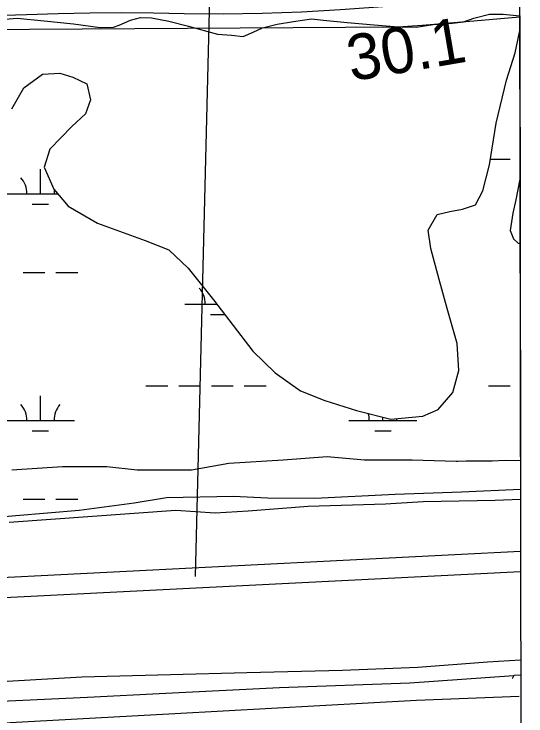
# Model space of a CAD drawing. Extents: x 3297772 to 3335630, y 634068 to 659439.
# Drawn here: x 3332702 to 3333452, y 644761 to 645791 of the extents above; entities that cross this region are included whole.
import ezdxf

# ---------------------------------------------------------------- set-up
doc = ezdxf.new("R2010")
doc.units = 0
for name, color, linetype in [('V-GRID-FRAM', 7, 'Continuous'), ('V-LEVE-TOET', 7, 'Continuous'), ('V-RIVR-EDGE', 7, 'Continuous'), ('V-RIVR-RANG', 7, 'Continuous'), ('V-ROAD-CNTR', 7, 'Continuous'), ('V-SITE-VEGE', 7, 'Continuous'), ('V-SURV-LINE', 7, 'Continuous'), ('V-TOPO-MAJR', 7, 'Continuous'), ('V-TOPO-MINR', 7, 'Continuous'), ('V-TOPO-SHOR', 7, 'Continuous'), ('V-WETL-SWMP', 7, 'Continuous')]:
    doc.layers.add(name, color=color, linetype=linetype)

msp = doc.modelspace()

# ---------------------------------------------------------------- linework, layer by layer
at = {"layer": 'V-GRID-FRAM'}
msp.add_lwpolyline([(3301870.2, 657630.6), (3333425.5, 657662.7), (3333452, 639478.7), (3301880.8, 639446.5), (3301870.2, 657630.6)], dxfattribs=at)
at = {"layer": 'V-LEVE-TOET'}
for points in [[(3332694.6, 645045.6), (3332938.6, 645062.9), (3332996.5, 645059.3), (3333045, 645062), (3333132.9, 645068.9), (3333246.3, 645072.3), (3333301.5, 645075.7), (3333407.1, 645077.6), (3333443.8, 645079.2)], [(3333444.2, 644843.2), (3333395.7, 644840.3), (3333293.6, 644832.2), (3333182.9, 644827.7), (3333042.9, 644824.3), (3332931.1, 644821.7), (3332801.3, 644817.9), (3332691.4, 644811.8)]]:
    msp.add_lwpolyline(points, dxfattribs=at)
at = {"layer": 'V-RIVR-EDGE'}
msp.add_spline([(3330448.9, 645637.2), (3330473.8, 645644.9), (3330485.1, 645645.6), (3330500.5, 645644.8), (3330522, 645643.6), (3330539.6, 645642.9), (3330563, 645640.3), (3330599.1, 645635.4), (3330611.9, 645635.4), (3330614.5, 645637.6), (3330621.8, 645642.7), (3330634.6, 645644.5), (3330658, 645645.1), (3330676.3, 645641.4), (3330692.7, 645638.8), (3330694.2, 645635.2), (3330695.6, 645630.4), (3330718.3, 645625.6), (3330735.1, 645623.7), (3330742.4, 645624.5), (3330747.5, 645627), (3330751.6, 645631.4), (3330753.4, 645635), (3330761.1, 645637.2), (3330782.3, 645640.8), (3330789.2, 645640.4), (3330794, 645636), (3330802.7, 645623.9), (3330811.5, 645611.5), (3330815.5, 645603.8), (3330821.3, 645595.7), (3330822, 645586.6), (3330823.1, 645574.9), (3330824.5, 645569.1), (3330830.7, 645561.4), (3330835.5, 645561), (3330841.3, 645561), (3330847.2, 645568.6), (3330850.1, 645570.1), (3330855.2, 645571.5), (3330860, 645570.4), (3330868, 645567.8), (3330875, 645567.5), (3330884.1, 645569.3), (3330893.3, 645573.3), (3330905.3, 645585.3), (3330916, 645598.1), (3330920.4, 645599.5), (3330923.7, 645599.9), (3330931.3, 645596.6), (3330964.5, 645574.2), (3330990.5, 645558), (3331006.9, 645555.8), (3331027.4, 645556.5), (3331050.4, 645560.8), (3331062.5, 645564.1), (3331069.8, 645569.2), (3331073.8, 645575.4), (3331079, 645581.6), (3331080.5, 645593.3), (3331079, 645606.8), (3331077.6, 645625.5), (3331079.1, 645633.5), (3331082, 645639.7), (3331082.4, 645641.5), (3331081, 645646.3), (3331082.1, 645648.1), (3331083.5, 645650.3), (3331090.5, 645655), (3331104.4, 645656.5), (3331108.8, 645656.4), (3331111.7, 645653.9), (3331119, 645651.3), (3331128.1, 645649.8), (3331136.9, 645646.1), (3331145.3, 645644.3), (3331147.9, 645645), (3331151.9, 645649), (3331154.1, 645652.7), (3331158.5, 645654.9), (3331161.8, 645654.1), (3331162.5, 645650.5), (3331163.9, 645638.4), (3331166.1, 645632.2), (3331174.9, 645626.7), (3331193.5, 645621.5), (3331201.2, 645621.5), (3331209.2, 645624), (3331216.9, 645631), (3331220.6, 645637.9), (3331221.3, 645645.2), (3331221.7, 645651.1), (3331219.5, 645660.9), (3331219.6, 645665.3), (3331221.8, 645667.9), (3331223.2, 645668.6), (3331224, 645672.2), (3331224.3, 645674.1), (3331226.9, 645674.8), (3331232.7, 645674.1), (3331234.2, 645675.9), (3331234.6, 645678.4), (3331237.5, 645678.8), (3331243, 645677.3), (3331252.5, 645675.5), (3331262.3, 645674.7), (3331276.6, 645675.8), (3331288.3, 645677.6), (3331300.7, 645680.8), (3331309.2, 645688.1), (3331324.6, 645709.3), (3331338.9, 645733), (3331346.2, 645741.4), (3331353.5, 645744.7), (3331367.4, 645747.2), (3331376.9, 645748.6), (3331391.2, 645748.2), (3331400.7, 645747.1), (3331406.5, 645746.7), (3331412.4, 645748.5), (3331415.3, 645750), (3331416.4, 645747.8), (3331418.6, 645746.3), (3331424.1, 645746.3), (3331431.8, 645750.3), (3331439.8, 645751), (3331465.1, 645752.4), (3331476, 645754.6), (3331481.5, 645759), (3331488.1, 645763.3), (3331494.3, 645765.9), (3331501.3, 645766.2), (3331514.4, 645765.5), (3331515.9, 645762.9), (3331517.7, 645761.1), (3331527.2, 645758.9), (3331536, 645758.8), (3331540.4, 645760.7), (3331541.1, 645762.5), (3331540.4, 645765), (3331536, 645768.3), (3331536, 645770.2), (3331537.1, 645771.6), (3331540, 645772), (3331557.6, 645767.9), (3331569.3, 645767.5), (3331581, 645767.5), (3331596, 645769.3), (3331613.5, 645772.2), (3331624.8, 645773.2), (3331630.3, 645771.4), (3331633.6, 645768.5), (3331638.7, 645767.7), (3331643.1, 645768.1), (3331648.6, 645770.6), (3331652.6, 645773.9), (3331660.3, 645775.7), (3331670.9, 645775.3), (3331678.2, 645771.3), (3331684.1, 645769.4), (3331691.4, 645768.7), (3331711.1, 645769.7), (3331753.5, 645776.2), (3331799.6, 645782.3), (3331827, 645783.3), (3331853, 645787.7), (3331887.7, 645791.2), (3331916.2, 645792.6), (3331931.2, 645791.9), (3331942.6, 645790), (3331955, 645781.9), (3331968.5, 645770.9), (3331978.3, 645765.4), (3332002.4, 645757.7), (3332022.2, 645755.8), (3332044.5, 645757.2), (3332072.2, 645760.4), (3332109.2, 645767.7), (3332134.1, 645770.9), (3332153.4, 645771.9), (3332163.7, 645772.6), (3332202.8, 645781), (3332228.8, 645786), (3332235, 645790), (3332245.6, 645799.1), (3332252.9, 645806.4), (3332260.3, 645810.4), (3332275.3, 645814), (3332289.5, 645815.5), (3332303.4, 645813.6), (3332324.6, 645804), (3332345.4, 645794.1), (3332361.1, 645788.6), (3332369.9, 645788.2), (3332383, 645788.9), (3332399.5, 645788.1), (3332415.2, 645784.8), (3332428.7, 645782.6), (3332441.5, 645781.8), (3332451.4, 645785.8), (3332467.5, 645793.8), (3332481.4, 645804), (3332490.5, 645806.9), (3332500.4, 645806.9), (3332507.4, 645806.5), (3332513.9, 645806.5), (3332520.9, 645807.2), (3332533.7, 645811.6), (3332542.5, 645814.8), (3332553.8, 645819.2), (3332575.4, 645826.1), (3332590, 645832.3), (3332610.2, 645843.2), (3332632.9, 645858.8), (3332647.2, 645866.5), (3332662.1, 645870.5), (3332681.2, 645871.2), (3332696.5, 645869.7), (3332706, 645868.5), (3332710.4, 645868.5), (3332715.9, 645870), (3332722.1, 645873.6), (3332725.4, 645873.6), (3332731.6, 645873.6), (3332741.5, 645868.8), (3332755.3, 645863.7), (3332763, 645864), (3332790.8, 645862.1), (3332817.5, 645861), (3332831.4, 645858.7), (3332832.8, 645859.5), (3332832.8, 645860.9), (3332831.4, 645863.1), (3332824.1, 645865.3), (3332823.7, 645867.5), (3332824.8, 645870.4), (3332827.7, 645872.3), (3332831, 645872.6), (3332842.7, 645870.8), (3332851.9, 645868.5), (3332854.4, 645868.5), (3332874.2, 645871.8), (3332895.4, 645875.4), (3332904.9, 645876.1), (3332914.8, 645876.1), (3332925, 645873.1), (3332938.1, 645867.2), (3332953.1, 645857.7), (3332967.7, 645851.8), (3332979.4, 645851.4), (3332987.8, 645848.8), (3332995.5, 645844.4), (3333020, 645841.8), (3333039, 645841.4), (3333050.7, 645843.2), (3333067.9, 645849), (3333089.1, 645857.4), (3333116.5, 645867.2), (3333136.3, 645871.5), (3333157.1, 645874), (3333175, 645874), (3333191.5, 645873.6), (3333203.5, 645875.4), (3333217.4, 645879), (3333230.6, 645878.9), (3333255.4, 645876), (3333267.5, 645876.3), (3333286.9, 645881.7), (3333304.1, 645884.2), (3333322.7, 645884.9), (3333341, 645886.7), (3333351.6, 645892.5), (3333363, 645899.8), (3333371.4, 645902), (3333390, 645904.1), (3333418.2, 645908.1), (3333442.6, 645911.2)], degree=3, dxfattribs=at)
at = {"layer": 'V-RIVR-RANG'}
msp.add_line((3332967.5, 644966), (3333004.6, 646465.6), dxfattribs=at)
at = {"layer": 'V-ROAD-CNTR'}
msp.add_lwpolyline([(3331179.9, 644989.5), (3331441, 645002.9), (3331521.1, 645001.9), (3331578.7, 644990.8), (3331648, 644970.9), (3331747.7, 644939.4), (3331871.6, 644891.7), (3331950.6, 644848.9), (3332022.3, 644803.4), (3332081, 644767.4), (3332152.5, 644748.8), (3332215.7, 644734.7), (3332344.8, 644731.4), (3332641.7, 644748.8), (3332937.5, 644764.7), (3333291.4, 644784.2), (3333441.9, 644790.5)], dxfattribs=at)
at = {"layer": 'V-SITE-VEGE'}
for p, q in [((3332675.5, 645782.2), (3332706.1, 645784.9)), ((3332706.1, 645784.9), (3332745.9, 645781)), ((3332872.5, 645781.6), (3332887.2, 645785.8)), ((3332887.2, 645785.8), (3332903, 645785)), ((3332903, 645785), (3332928.6, 645780.4)), ((3333111.2, 645779.8), (3333137.5, 645783.6)), ((3333137.5, 645783.6), (3333155.3, 645781.6)), ((3333360.4, 645779.5), (3333375.5, 645784.5)), ((3333375.5, 645784.5), (3333398.7, 645790.7)), ((3333398.7, 645790.7), (3333418.8, 645790.6)), ((3333418.8, 645790.6), (3333442.8, 645788)), ((3333442.8, 645788), (3333443.8, 645135.6)), ((3332745.9, 645781), (3332788.9, 645776.3)), ((3332788.9, 645776.3), (3332828, 645771.2)), ((3332847.7, 645771.6), (3332855.8, 645774.6)), ((3332855.8, 645774.6), (3332872.5, 645781.6)), ((3332928.6, 645780.4), (3332957.6, 645773)), ((3332957.6, 645773), (3333000.1, 645761.3)), ((3333065.9, 645770.5), (3333087.2, 645775.9)), ((3333087.2, 645775.9), (3333111.2, 645779.8)), ((3333155.3, 645781.6), (3333189.8, 645778.5)), ((3333189.8, 645778.5), (3333229.6, 645775)), ((3333229.6, 645775), (3333264.8, 645771.8)), ((3333264.8, 645771.8), (3333291.1, 645771.4)), ((3333291.1, 645771.4), (3333315.9, 645775.3)), ((3333315.9, 645775.3), (3333344.1, 645777.6)), ((3333344.1, 645777.6), (3333360.4, 645779.5)), ((3332828, 645771.2), (3332847.7, 645771.6)), ((3333037.7, 645757.8), (3333052.4, 645764.4)), ((3333052.4, 645764.4), (3333065.9, 645770.5)), ((3333000.1, 645761.3), (3333020.6, 645759.7)), ((3333020.6, 645759.7), (3333037.7, 645757.8)), ((3333096, 645136.6), (3333016.5, 645131.6)), ((3333160.7, 645141.5), (3333096, 645136.6)), ((3333215.4, 645136.6), (3333160.7, 645141.5)), ((3333285, 645136.6), (3333215.4, 645136.6)), ((3333349.7, 645134.5), (3333285, 645136.6)), ((3333352.2, 645134.5), (3333349.7, 645134.5)), ((3333364.4, 645134.8), (3333352.2, 645134.5)), ((3333369.9, 645134.8), (3333364.4, 645134.8)), ((3333389.2, 645135.1), (3333369.9, 645134.8)), ((3333402.4, 645135), (3333389.2, 645135.1)), ((3333421.6, 645135.8), (3333402.4, 645135)), ((3333443.8, 645135.6), (3333421.6, 645135.8)), ((3332772.9, 645126.6), (3332698.3, 645121.6)), ((3332837.5, 645126.6), (3332772.9, 645126.6)), ((3332882.3, 645121.6), (3332837.5, 645126.6)), ((3333016.5, 645131.6), (3332961.8, 645121.6)), ((3332897.2, 645121.6), (3332882.3, 645121.6)), ((3332961.8, 645121.6), (3332897.2, 645121.6))]:
    msp.add_line(p, q, dxfattribs=at)
at = {"layer": 'V-SURV-LINE'}
for points in [[(3332384.6, 644949.2), (3333444, 645002.7)], [(3333444, 644972.7), (3332386.1, 644919.2)]]:
    msp.add_lwpolyline(points, dxfattribs=at)
at = {"layer": 'V-TOPO-MAJR'}
msp.add_lwpolyline([(3332569.6, 645767.7), (3333264.8, 645771.9), (3333299.7, 645774.4), (3333334.7, 645777.2), (3333369.6, 645780.2), (3333442.8, 645786.7)], dxfattribs=at)
at = {"layer": 'V-TOPO-MINR'}
msp.add_lwpolyline([(3332671.3, 645788.4), (3332719.9, 645790.3), (3332766.4, 645791.8), (3332812.9, 645792.7), (3332859.4, 645792.8), (3332905.9, 645792.4), (3332951.1, 645791.6), (3333008.3, 645791.3), (3333065.6, 645792), (3333122.8, 645794.2), (3333180, 645797.4), (3333256, 645802.6), (3333275.2, 645804), (3333294.3, 645805.6), (3333313.4, 645807.5), (3333332.5, 645809.5), (3333442.8, 645822)], dxfattribs=at)
at = {"layer": 'V-TOPO-SHOR'}
msp.add_line((3333434, 644820.6), (3333431.9, 644815.8), dxfattribs=at)
for points in [[(3332809.3, 644788.7), (3332924.1, 644794.8), (3333090.9, 644803.1), (3333281.9, 644809.9), (3333434, 644820.6)], [(3333444.2, 644821), (3333434, 644820.6)], [(3332088.3, 644799.2), (3332107.4, 644791.8), (3332140.4, 644780.5), (3332197.2, 644769.9), (3332304.5, 644763.6), (3332400.6, 644769.3), (3332538.6, 644776.2), (3332651, 644781.5), (3332809.3, 644788.7)]]:
    msp.add_lwpolyline(points, dxfattribs=at)
at = {"layer": 'V-WETL-SWMP'}
for p, q in [((3333436, 645734), (3333442.3, 645764.3)), ((3333442.3, 645764.3), (3333442.8, 645766.7)), ((3333442.8, 645766.7), (3333443.2, 645548.7)), ((3333423.4, 645693.7), (3333436, 645734)), ((3332716.1, 645682.5), (3332743.4, 645702.4)), ((3332743.4, 645702.4), (3332769, 645703.9)), ((3332769, 645703.9), (3332787.8, 645698.1)), ((3332787.8, 645698.1), (3332808.2, 645688.2)), ((3333408.1, 645630.5), (3333423.4, 645693.7)), ((3332698.3, 645651.7), (3332716.1, 645682.5)), ((3332808.2, 645688.2), (3332813.9, 645665.1)), ((3332813.9, 645665.1), (3332806.6, 645644.2)), ((3332806.6, 645644.2), (3332786.2, 645625.9)), ((3333398.6, 645569.8), (3333408.1, 645630.5)), ((3332786.2, 645625.9), (3332754.2, 645592.5)), ((3332754.2, 645592.5), (3332745.8, 645566.4)), ((3333399.9, 645578), (3333428.9, 645578)), ((3332745.8, 645566.4), (3332759.9, 645533.9)), ((3333388.6, 645531.6), (3333398.6, 645569.8)), ((3332740.4, 645527.3), (3332740.4, 645563.3)), ((3333443.2, 645548.7), (3333437.2, 645518.3)), ((3332690.4, 645527.3), (3332765.4, 645527.3)), ((3332759.9, 645533.9), (3332780.8, 645508.8)), ((3333378.2, 645510.7), (3333388.6, 645531.6)), ((3333437.2, 645518.3), (3333433, 645498.5)), ((3332728.4, 645511.8), (3332752.4, 645511.8)), ((3332780.8, 645508.8), (3332824.2, 645484.1)), ((3333340.5, 645501.3), (3333358.8, 645504.4)), ((3333358.8, 645504.4), (3333378.2, 645510.7)), ((3333308.5, 645473.6), (3333321.7, 645496.6)), ((3333321.7, 645496.6), (3333340.5, 645501.3)), ((3333433, 645498.5), (3333428.8, 645473.4)), ((3332824.2, 645484.1), (3332893.7, 645458.4)), ((3333312.7, 645447), (3333308.5, 645473.6)), ((3333428.8, 645473.4), (3333433.5, 645461.3)), ((3332893.7, 645458.4), (3332928.8, 645444.8)), ((3333433.5, 645461.3), (3333440.8, 645454.5)), ((3333440.8, 645454.5), (3333443.3, 645454.3)), ((3333443.3, 645454.3), (3333443.8, 645093.4)), ((3332928.8, 645444.8), (3332957, 645418.1)), ((3333324.7, 645401.4), (3333312.7, 645447)), ((3332715, 645411.8), (3332747, 645411.8)), ((3332763, 645411.8), (3332795, 645411.8)), ((3332957, 645418.1), (3332994.1, 645371.5)), ((3333336.7, 645359.1), (3333324.7, 645401.4)), ((3332994.1, 645371.5), (3333051.5, 645296.1)), ((3332951.8, 645365.4), (3332998.7, 645365.4)), ((3332989.8, 645350), (3333010.5, 645350)), ((3333351.2, 645307.3), (3333336.7, 645359.1)), ((3333353.8, 645268), (3333351.2, 645307.3)), ((3333051.5, 645296.1), (3333084.4, 645264.7)), ((3333344.9, 645235.6), (3333353.8, 645268)), ((3333084.4, 645264.7), (3333121.5, 645238)), ((3332895, 645245.3), (3332927, 645245.3)), ((3332943, 645245.3), (3332975, 645245.3)), ((3332991, 645245.3), (3333023, 645245.3)), ((3333039, 645245.3), (3333071, 645245.3)), ((3333121.5, 645238), (3333157.1, 645223.8)), ((3333396.9, 645245.3), (3333428.9, 645245.3)), ((3332740.4, 645194.6), (3332740.4, 645230.6)), ((3333323.4, 645210.5), (3333344.9, 645235.6)), ((3333157.1, 645223.8), (3333203.6, 645209.1)), ((3333203.6, 645209.1), (3333253.8, 645196.5)), ((3333300.9, 645201.1), (3333323.4, 645210.5)), ((3333242.3, 645194.6), (3333242.3, 645199.4)), ((3333253.8, 645196.5), (3333300.9, 645201.1)), ((3332690.4, 645194.6), (3332790.4, 645194.6)), ((3333192.3, 645194.6), (3333292.3, 645194.6)), ((3332728.4, 645179.2), (3332752.4, 645179.2)), ((3333230.3, 645179.2), (3333254.3, 645179.2)), ((3333443.8, 645093.4), (3333357.3, 645089.6)), ((3333023.5, 645083.2), (3332925.2, 645081.3)), ((3333073.2, 645080.6), (3333023.5, 645083.2)), ((3333260.5, 645086.1), (3333142.8, 645080)), ((3333357.3, 645089.6), (3333260.5, 645086.1)), ((3332715, 645079.2), (3332747, 645079.2)), ((3332763, 645079.2), (3332795, 645079.2)), ((3332877.6, 645073.5), (3332797, 645062.6)), ((3332925.2, 645081.3), (3332877.6, 645073.5)), ((3333142.8, 645080), (3333073.2, 645080.6)), ((3332797, 645062.6), (3332704.4, 645054.8)), ((3332704.4, 645054.8), (3332547.5, 645041.4))]:
    msp.add_line(p, q, dxfattribs=at)
for centre, start, end in [((3332685.2, 645527.7), 359.2282, 40.7718), ((3332795.6, 645527.7), 171.5993, 180.7718), ((3332946.6, 645365.9), 359.2282, 40.7718), ((3332685.2, 645195.1), 359.2282, 40.7718), ((3332795.6, 645195.1), 139.2282, 180.7718), ((3333187.1, 645195.1), 359.2282, 15.9273), ((3333297.5, 645195.1), 176.3325, 180.7718)]:
    msp.add_arc(centre, 35.2, start, end, dxfattribs=at)

# ---------------------------------------------------------------- texts
at = {"layer": 'V-RIVR-RANG'}
msp.add_text('30.1', height=67, rotation=9.6883, dxfattribs=at).set_placement((3333195.8, 645691.9))

doc.saveas('drawing.dxf')
